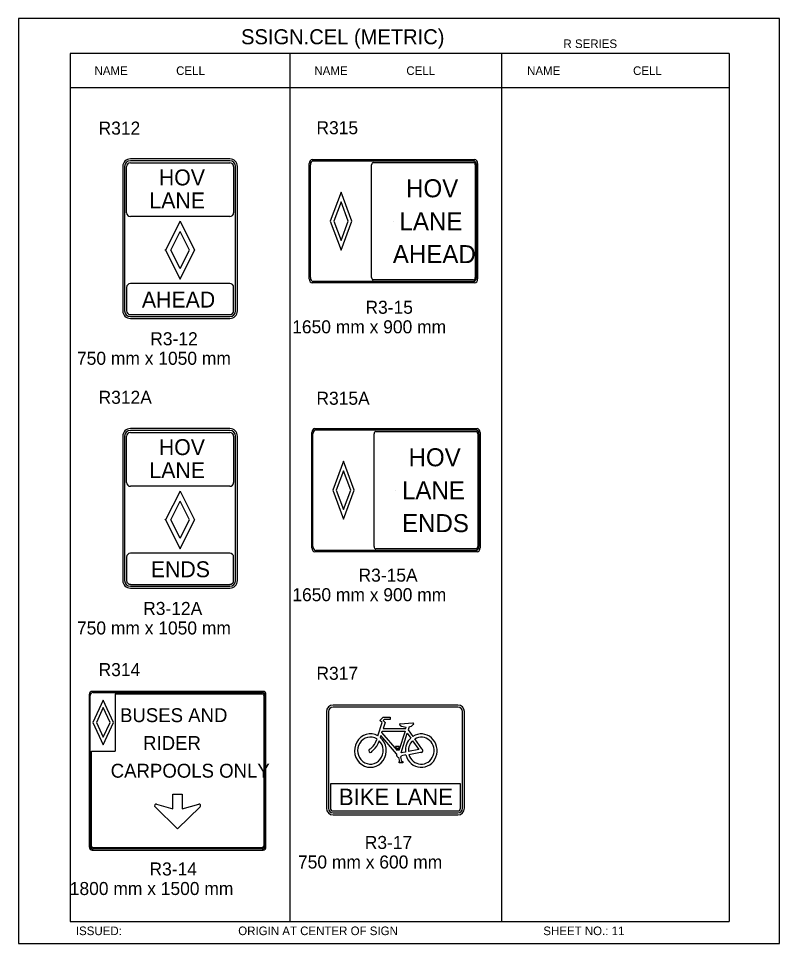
# Model space of a CAD drawing. Extents: x -12 to 6962, y -3756 to 679.
# Drawn here: x 812.1 to 987.4, y -5 to 208 of the extents above; entities that cross this region are included whole.
import ezdxf

# ---------------------------------------------------------------- set-up
doc = ezdxf.new("R2010")
doc.units = 0
for name, color, linetype in [('Level 1', 7, 'Continuous'), ('Level 2', 7, 'Continuous'), ('Level 3', 7, 'Continuous'), ('Level 63', 7, 'Continuous')]:
    doc.layers.add(name, color=color, linetype=linetype)

msp = doc.modelspace()

# ---------------------------------------------------------------- linework, layer by layer
at = {"layer": 'Level 1'}
for p, q in [((975.73, 200), (823.97, 200)), ((823.97, 200), (823.97, 0)), ((874.56, 200), (874.56, 0)), ((923.34, 200), (923.34, 0)), ((975.73, 200), (975.73, 0)), ((975.73, 192.08), (823.97, 192.08)), ((860.76, 175.26), (837.86, 175.26)), ((837.86, 174.82), (860.76, 174.82)), ((879.97, 175.22), (916.91, 175.22)), ((893.81, 174.87), (916.91, 174.87)), ((836.54, 173.95), (836.54, 140.7)), ((836.98, 163.29), (836.98, 173.95)), ((861.64, 173.95), (861.64, 163.29)), ((862.08, 140.7), (862.08, 173.95)), ((879.32, 148.35), (879.32, 174.34)), ((893.42, 148.35), (893.42, 174.34)), ((917.3, 174.34), (917.3, 148.35)), ((917.57, 174.34), (917.57, 148.35)), ((860.76, 162.41), (837.86, 162.41)), ((898.44, 161.35), (898.44, 161.35)), ((849.31, 157.32), (849.31, 157.32)), ((916.91, 147.48), (879.97, 147.48)), ((916.91, 147.83), (893.81, 147.83)), ((836.98, 146.11), (836.98, 140.7)), ((860.76, 146.99), (837.86, 146.99)), ((861.64, 140.7), (861.64, 146.11)), ((837.86, 139.82), (860.76, 139.82)), ((837.86, 139.39), (860.76, 139.39)), ((860.76, 113.13), (837.86, 113.13)), ((880.54, 113.25), (917.48, 113.25)), ((836.54, 111.82), (836.54, 78.57)), ((836.98, 101.15), (836.98, 111.82)), ((837.86, 112.69), (860.76, 112.69)), ((861.64, 111.82), (861.64, 101.15)), ((862.08, 78.57), (862.08, 111.82)), ((879.89, 86.38), (879.89, 112.37)), ((893.99, 86.38), (893.99, 112.37)), ((894.38, 112.9), (917.48, 112.9)), ((917.87, 112.37), (917.87, 86.38)), ((918.14, 112.37), (918.14, 86.38)), ((860.76, 100.28), (837.86, 100.28)), ((899.01, 99.38), (899.01, 99.38)), ((899.01, 99.38), (899.01, 99.38)), ((849.31, 95.19), (849.31, 95.19)), ((917.48, 85.51), (880.54, 85.51)), ((917.48, 85.86), (894.38, 85.86)), ((836.98, 83.98), (836.98, 78.57)), ((860.76, 84.86), (837.86, 84.86)), ((861.64, 78.57), (861.64, 83.98)), ((837.86, 77.69), (860.76, 77.69)), ((837.86, 77.26), (860.76, 77.26)), ((828.63, 17.41), (828.63, 52.09)), ((829.26, 52.77), (868.21, 52.77)), ((834.35, 52.5), (868.21, 52.5)), ((834.35, 52.5), (834.35, 39.29)), ((868.58, 52.09), (868.58, 17.41)), ((868.83, 52.09), (868.83, 17.41)), ((913.29, 49.43), (884.54, 49.43)), ((883.48, 48.37), (883.48, 26.1)), ((895.34, 46.36), (896.05, 47.1)), ((896.05, 47.1), (897.67, 47.1)), ((897.67, 47.1), (897.67, 46.54)), ((914.35, 26.1), (914.35, 48.37)), ((894.86, 42.77), (895.84, 45.83)), ((895.84, 45.83), (895.34, 46.36)), ((896.51, 45.89), (896.07, 44.49)), ((896.28, 46.54), (896.09, 46.36)), ((896.09, 46.36), (896.51, 45.89)), ((897.67, 46.54), (896.28, 46.54)), ((900.03, 45.59), (902.93, 45.75)), ((901.3, 44.49), (901.39, 44.81)), ((902.04, 44.83), (901.85, 44.21)), ((895.55, 42.88), (895.4, 42.41)), ((899.16, 38.65), (895.55, 42.88)), ((895.78, 43.58), (895.86, 43.83)), ((899.36, 39.39), (895.78, 43.58)), ((895.86, 43.83), (901.11, 43.83)), ((896.07, 44.49), (901.3, 44.49)), ((901.11, 43.83), (899.72, 39.41)), ((900.2, 38.89), (901.62, 43.44)), ((901.62, 43.44), (902.45, 42.29)), ((901.85, 44.21), (902.93, 42.67)), ((894.65, 42.07), (894.55, 41.8)), ((895.13, 41.58), (895.17, 41.66)), ((902.85, 41.66), (904.31, 39.62)), ((904.97, 39.78), (903.35, 42.07)), ((828.88, 17.41), (828.88, 39.29)), ((828.88, 39.29), (834.35, 39.29)), ((893.4, 40.02), (893.13, 39.8)), ((893.54, 39.29), (893.79, 39.52)), ((899.78, 40.35), (898.95, 40.35)), ((898.95, 40.35), (898.95, 40.04)), ((898.95, 40.04), (899.22, 40.04)), ((899.22, 40.04), (899.36, 39.39)), ((899.72, 39.41), (899.59, 40.04)), ((899.59, 40.04), (899.78, 40.04)), ((899.78, 40.04), (899.78, 40.35)), ((901.2, 39.05), (900.2, 38.89)), ((901.32, 38.4), (900.32, 38.22)), ((904.31, 39.62), (901.91, 39.19)), ((902.01, 38.52), (904.68, 39.01)), ((898.91, 37.23), (898.91, 37.23)), ((899.93, 36.87), (899.72, 37.82)), ((899.74, 36.56), (899.74, 36.87)), ((899.74, 36.87), (899.93, 36.87)), ((900.57, 36.56), (899.74, 36.56)), ((900.07, 37.92), (900.3, 36.87)), ((900.3, 36.87), (900.57, 36.87)), ((900.57, 36.87), (900.57, 36.56)), ((848.73, 34.75), (848.73, 34.75)), ((913.9, 31.75), (883.93, 31.75)), ((883.93, 31.75), (883.93, 26.1)), ((913.9, 26.1), (913.9, 31.75)), ((847.64, 25.99), (847.64, 29.35)), ((847.64, 29.35), (849.82, 29.35)), ((849.82, 29.35), (849.82, 25.99)), ((848.73, 21.34), (843.55, 26.4)), ((843.86, 27.04), (847.64, 25.99)), ((853.92, 26.4), (848.73, 21.34)), ((849.82, 25.99), (853.59, 27.04)), ((884.54, 25.49), (913.29, 25.49)), ((884.54, 25.03), (913.29, 25.03)), ((868.21, 17.01), (829.26, 17.01)), ((868.21, 16.74), (829.26, 16.74)), ((823.97, 0), (975.73, 0))]:
    msp.add_line(p, q, dxfattribs=at)
for points in [[(886.37, 168.02), (883.89, 161.35), (886.37, 154.67), (888.85, 161.35)], [(886.37, 165.8), (884.72, 161.35), (886.37, 156.9), (888.02, 161.35)], [(886.94, 106.05), (884.46, 99.38), (886.94, 92.7), (889.42, 99.38)], [(886.94, 103.83), (885.29, 99.38), (886.94, 94.93), (888.6, 99.38)], [(831.61, 51.04), (829.23, 45.89), (831.61, 40.74), (834, 45.89)], [(831.61, 49.33), (830.02, 45.89), (831.61, 42.46), (833.21, 45.89)]]:
    msp.add_lwpolyline(points, close=True, dxfattribs=at)
for centre, radius, start, end in [((884.54, 48.37), 1.06, 90, 180), ((913.29, 48.37), 1.06, 0, 90), ((884.54, 26.1), 1.06, 180, 270), ((884.54, 26.1), 0.608, 180, 270), ((913.29, 26.1), 0.608, 270, 0), ((913.29, 26.1), 1.06, 270, 0)]:
    msp.add_arc(centre, radius, start, end, dxfattribs=at)
for centre, major_axis, ratio, start_param, end_param in [((837.86, 173.95), (-1.32, 0), 0.993763, 4.712389, 6.283185), ((837.86, 173.95), (-0.88, 0), 0.993763, 4.712389, 6.283185), ((860.76, 173.95), (1.32, 0), 0.993763, 0, 1.570796), ((860.76, 173.95), (-0.88, 0), 0.993763, 3.141593, 4.712389), ((879.97, 174.34), (0, -0.877), 0.743304, 3.141593, 4.712389), ((893.81, 174.34), (0, -0.525), 0.743304, 3.141593, 4.712389), ((916.91, 174.34), (0, 0.877), 0.743304, 4.712389, 6.283185), ((916.91, 174.34), (0, 0.525), 0.743304, 4.712389, 6.283185), ((837.86, 163.29), (0.88, 0), 0.993763, 3.141593, 4.712389), ((860.76, 163.29), (0.882, 0), 0.993763, 4.712389, 6.283185), ((879.97, 148.35), (0, -0.877), 0.743304, 4.712389, 6.283185), ((893.81, 148.35), (0, -0.525), 0.743304, 4.712389, 6.283185), ((916.91, 148.35), (0, 0.877), 0.743304, 3.141593, 4.712389), ((916.91, 148.35), (0, 0.525), 0.743304, 3.141593, 4.712389), ((837.86, 146.11), (-0.88, 0), 0.993763, 4.712389, 6.283185), ((860.76, 146.11), (0.884, 0), 0.993763, 0, 1.570796), ((837.86, 140.7), (1.32, 0), 0.993763, 3.141593, 4.712389), ((837.86, 140.7), (-0.88, 0), 0.993763, 0, 1.570796), ((860.76, 140.7), (1.32, 0), 0.993763, 4.712389, 6.283185), ((860.76, 140.7), (0.88, 0), 0.993763, 4.712389, 6.283185), ((837.86, 111.82), (-1.32, 0), 0.993763, 4.712389, 6.283185), ((860.76, 111.82), (1.32, 0), 0.993763, 0, 1.570796), ((880.54, 112.37), (0, -0.877), 0.743304, 3.141593, 4.712389), ((917.48, 112.37), (0, 0.877), 0.743304, 4.712389, 6.283185), ((837.86, 111.82), (-0.88, 0), 0.993763, 4.712389, 6.283185), ((860.76, 111.82), (-0.88, 0), 0.993763, 3.141593, 4.712389), ((894.38, 112.37), (0, -0.525), 0.743304, 3.141593, 4.712389), ((917.48, 112.37), (0, 0.525), 0.743304, 4.712389, 6.283185), ((837.86, 101.15), (0.88, 0), 0.993763, 3.141593, 4.712389), ((860.76, 101.15), (0.882, 0), 0.993763, 4.712389, 6.283185), ((880.54, 86.38), (0, -0.877), 0.743304, 4.712389, 6.283185), ((894.38, 86.38), (0, -0.525), 0.743304, 4.712389, 6.283185), ((917.48, 86.38), (0, 0.877), 0.743304, 3.141593, 4.712389), ((917.48, 86.38), (0, 0.525), 0.743304, 3.141593, 4.712389), ((837.86, 83.98), (-0.88, 0), 0.993763, 4.712389, 6.283185), ((860.76, 83.98), (0.884, 0), 0.993763, 0, 1.570796), ((837.86, 78.57), (1.32, 0), 0.993763, 3.141593, 4.712389), ((837.86, 78.57), (-0.88, 0), 0.993763, 0, 1.570796), ((860.76, 78.57), (1.32, 0), 0.993763, 4.712389, 6.283185), ((860.76, 78.57), (0.88, 0), 0.993763, 4.712389, 6.283185), ((829.26, 52.09), (0, -0.677), 0.9275, 3.141593, 4.712389), ((868.21, 52.09), (0, 0.677), 0.9275, 4.712389, 6.283185), ((868.21, 52.09), (0, 0.405), 0.9275, 4.712389, 6.283185), ((900.04, 45.39), (0, -0.186), 0.94945, 3.226888, 5.815521), ((901.53, 48.28), (0, 3.48), 0.949451, 2.643723, 3.097911), ((901.73, 46.66), (0, 1.86), 0.949451, 3.318736, 4.000032), ((902.93, 45.56), (0, -0.187), 0.94945, 0.878905, 3.099137), ((893.14, 39.39), (0, -3.85), 0.949451, 2.649265, 8.760057), ((893.14, 39.39), (0, -3.11), 0.949451, 2.607497, 8.671871), ((904.85, 39.38), (0, -3.85), 0.949451, 4.971468, 9.974568), ((904.85, 39.38), (0, -3.11), 0.949451, 4.993104, 9.954949), ((890.98, 43.05), (0, 3.96), 0.949451, 3.838751, 4.389585), ((891.12, 42.94), (0, 4.43), 0.949451, 3.829085, 4.399537), ((904.85, 39.38), (0, 3.85), 0.949451, 0.718242, 1.656295), ((904.79, 39.4), (0, 3.05), 0.949451, 0.729351, 1.640231), ((893.15, 39.38), (0, 0.418), 0.949451, 0.027423, 4.490459), ((899.76, 38.46), (0, -0.644), 0.949451, 4.421521, 6.222869), ((904.85, 39.38), (0, -0.412), 0.949451, 5.793081, 9.148728), ((899.72, 38.5), (0, 0.686), 0.949451, 3.697306, 4.278972), ((843.78, 26.68), (0, 0.376), 0.9275, 6.033564, 8.681553), ((853.68, 26.68), (0, -0.376), 0.9275, 0.743224, 3.391214), ((829.26, 17.41), (0, -0.677), 0.9275, 4.712389, 6.283185), ((829.26, 17.41), (0, -0.405), 0.9275, 4.712389, 6.283185), ((868.21, 17.41), (0, 0.677), 0.9275, 3.141593, 4.712389), ((868.21, 17.41), (0, 0.405), 0.9275, 3.141593, 4.712389)]:
    msp.add_ellipse(centre, major_axis=major_axis, ratio=ratio, start_param=start_param, end_param=end_param, dxfattribs=at)
at = {"layer": 'Level 3'}
for p, q in [((860.76, 175.7), (837.86, 175.7)), ((879.76, 175.57), (917.12, 175.57)), ((836.1, 173.95), (836.1, 140.7)), ((862.52, 140.7), (862.52, 173.95)), ((879.06, 148.07), (879.06, 174.62)), ((917.83, 174.62), (917.83, 148.07)), ((849.3, 161.32), (845.94, 154.7)), ((849.3, 161.32), (852.65, 154.7)), ((847.15, 154.7), (849.3, 158.97)), ((851.44, 154.7), (849.3, 158.97)), ((845.93, 154.7), (845.9, 154.7)), ((845.94, 154.7), (849.3, 148.03)), ((849.3, 150.49), (847.15, 154.7)), ((849.29, 148.03), (852.64, 154.7)), ((849.3, 150.49), (851.44, 154.7)), ((917.12, 147.12), (879.76, 147.12)), ((837.86, 138.95), (860.76, 138.95)), ((860.76, 113.57), (837.86, 113.57)), ((880.34, 113.6), (917.69, 113.6)), ((836.1, 111.82), (836.1, 78.57)), ((862.52, 78.57), (862.52, 111.82)), ((879.63, 86.1), (879.63, 112.65)), ((918.4, 112.65), (918.4, 86.1)), ((849.3, 99.19), (845.94, 92.57)), ((849.3, 99.19), (852.65, 92.57)), ((847.15, 92.57), (849.3, 96.83)), ((851.44, 92.57), (849.3, 96.83)), ((845.93, 92.57), (845.9, 92.57)), ((845.94, 92.57), (849.3, 85.9)), ((849.3, 88.36), (847.15, 92.57)), ((849.29, 85.89), (852.64, 92.57)), ((849.3, 88.36), (851.44, 92.57)), ((917.69, 85.15), (880.34, 85.15)), ((837.86, 76.82), (860.76, 76.82)), ((828.38, 52.31), (828.38, 17.2)), ((868.41, 53.04), (829.06, 53.04)), ((869.09, 17.2), (869.09, 52.31)), ((913.29, 49.89), (884.54, 49.89)), ((883.02, 48.37), (883.02, 26.1)), ((914.81, 26.1), (914.81, 48.37)), ((884.54, 24.58), (913.29, 24.58)), ((829.06, 16.47), (868.41, 16.47))]:
    msp.add_line(p, q, dxfattribs=at)
for points in [[(845.9, 154.7), (845.9, 154.73), (845.95, 154.73), (845.93, 154.7)], [(845.9, 92.57), (845.9, 92.6), (845.95, 92.6), (845.93, 92.57)]]:
    msp.add_lwpolyline(points, dxfattribs=at)
for centre, start, end in [((884.54, 48.37), 90, 180), ((913.29, 48.37), 0, 90), ((884.54, 26.1), 180, 270), ((913.29, 26.1), 270, 0)]:
    msp.add_arc(centre, 1.52, start, end, dxfattribs=at)
for centre, major_axis, ratio, start_param, end_param in [((837.86, 173.95), (-1.76, 0), 0.993763, 4.712389, 6.283185), ((860.76, 173.95), (1.76, 0), 0.993763, 0, 1.570796), ((879.76, 174.62), (0, -0.948), 0.743304, 3.141593, 4.712389), ((917.12, 174.62), (0, 0.948), 0.743304, 4.712389, 6.283185), ((879.76, 148.07), (0, -0.948), 0.743304, 4.712389, 6.283185), ((917.12, 148.07), (0, 0.948), 0.743304, 3.141593, 4.712389), ((837.86, 140.7), (1.76, 0), 0.993763, 3.141593, 4.712389), ((860.76, 140.7), (1.76, 0), 0.993763, 4.712389, 6.283185), ((837.86, 111.82), (-1.76, 0), 0.993763, 4.712389, 6.283185), ((860.76, 111.82), (1.76, 0), 0.993763, 0, 1.570796), ((880.34, 112.65), (0, -0.948), 0.743304, 3.141593, 4.712389), ((917.69, 112.65), (0, 0.948), 0.743304, 4.712389, 6.283185), ((880.34, 86.1), (0, -0.948), 0.743304, 4.712389, 6.283185), ((917.69, 86.1), (0, 0.948), 0.743304, 3.141593, 4.712389), ((837.86, 78.57), (1.76, 0), 0.993763, 3.141593, 4.712389), ((860.76, 78.57), (1.76, 0), 0.993763, 4.712389, 6.283185), ((829.06, 52.31), (0, -0.731), 0.9275, 3.141593, 4.712389), ((868.41, 52.31), (0, 0.731), 0.9275, 4.712389, 6.283185), ((829.06, 17.2), (0, -0.731), 0.9275, 4.712389, 6.283185), ((868.41, 17.2), (0, 0.731), 0.9275, 3.141593, 4.712389)]:
    msp.add_ellipse(centre, major_axis=major_axis, ratio=ratio, start_param=start_param, end_param=end_param, dxfattribs=at)
at = {"layer": 'Level 63'}
msp.add_lwpolyline([(812.09, -5.05), (987.36, -5.05), (987.36, 208.05), (812.09, 208.05)], close=True, dxfattribs=at)

# ---------------------------------------------------------------- texts
at = {"layer": 'Level 1'}
for s, height, p in [('HOV', 3.664, (844.42, 169.6)), ('HOV', 4.149, (901.35, 166.86)), ('LANE', 3.664, (842.24, 164.3)), ('LANE', 4.149, (899.84, 159.27)), ('AHEAD', 4.149, (898.3, 151.69)), ('AHEAD', 3.664, (840.51, 141.46)), ('HOV', 3.664, (844.42, 107.47)), ('HOV', 4.149, (901.92, 104.89)), ('LANE', 3.664, (842.24, 102.17)), ('LANE', 4.149, (900.41, 97.3)), ('ENDS', 4.149, (900.41, 89.72)), ('ENDS', 3.664, (842.57, 79.33)), ('  BUSES AND', 3.2002, (833.1, 45.95)), ('    RIDER', 3.2, (836.04, 39.55)), ('CARPOOLS ONLY', 3.2003, (833.33, 33.15)), ('BIKE LANE', 3.8, (885.89, 26.83))]:
    msp.add_text(s, height=height, dxfattribs=at).set_placement(p)
at = {"layer": 'Level 2'}
for s, p in [('R312', (830.54, 181.3)), ('R315', (880.71, 181.39)), ('R312A', (830.54, 119.28)), ('R315A', (880.71, 119.06)), ('R314', (830.54, 56.55)), ('R317', (880.71, 55.7))]:
    msp.add_text(s, height=3, dxfattribs=at).set_placement(p)
at = {"layer": 'Level 3'}
for s, height, p in [('SSIGN.CEL (METRIC)', 3.4642, (863.35, 202.11)), ('R SERIES', 1.979, (937.6, 201.24)), ('NAME', 1.98, (829.6, 195.04)), ('CELL', 1.98, (848.4, 195.04)), ('NAME', 1.98, (880.23, 195.04)), ('CELL', 1.98, (901.42, 195.04)), ('NAME', 1.98, (929.23, 195.04)), ('CELL', 1.98, (953.63, 195.04)), ('R3-15', 3, (892, 140.02)), ('1650 mm x 900 mm', 3, (875.13, 135.52)), ('R3-12', 3, (842.44, 132.77)), ('750 mm x 1050 mm', 3, (825.56, 128.27)), ('R3-15A', 3, (890.41, 78.31)), ('1650 mm x 900 mm', 3, (875.16, 73.81)), ('R3-12A', 3, (840.81, 70.64)), ('750 mm x 1050 mm', 3, (825.56, 66.14)), ('R3-17', 3, (891.84, 16.73)), ('750 mm x 600 mm', 3, (876.46, 12.23)), ('R3-14', 3, (842.27, 10.62)), ('1800 mm x 1500 mm', 3, (823.9, 6.12)), ('ISSUED:', 1.98, (825.31, -3.12)), ('ORIGIN AT CENTER OF SIGN', 1.9795, (862.7, -3.12)), ('SHEET NO.: 11', 1.9795, (932.96, -3.12))]:
    msp.add_text(s, height=height, dxfattribs=at).set_placement(p)

doc.saveas('drawing.dxf')
